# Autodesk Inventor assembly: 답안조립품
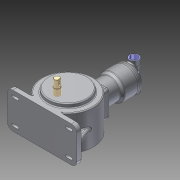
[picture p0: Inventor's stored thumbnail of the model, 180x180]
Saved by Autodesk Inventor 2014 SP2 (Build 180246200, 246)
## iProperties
Created: 2015-06
Part Number: 답안조립품
Document SubType Name: Assembly
Designer: 201-01
Author: 201-01
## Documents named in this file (10)
- C:\Users\201-01\Desktop\450605V1032\답안조립품.iam
- C:\Users\201-01\Desktop\450605V1032\답안도면.ipt
- C:\Users\201-01\Desktop\450605V1032\커넥팅 로드.ipt
- C:\Users\201-01\Desktop\450605V1032\피스톤 핀.ipt
- C:\Users\201-01\Desktop\450605V1032\피스톤.ipt
- C:\Users\201-01\Desktop\450605V1032\실린더.ipt
- C:\Users\201-01\Desktop\450605V1032\실린더헤드.ipt
- C:\Users\201-01\Desktop\450605V1032\메인 크랭크 축-구동부.ipt
- C:\Users\201-01\Desktop\450605V1032\크랭크 서브축.ipt
- C:\Users\201-01\Desktop\450605V1032\베어링 6204.ipt
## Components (2 placed, 2 different names)
1. 피스톤 핀:1
2. 피스톤:1
